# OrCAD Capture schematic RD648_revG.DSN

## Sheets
1 Mechanical Parts: size B
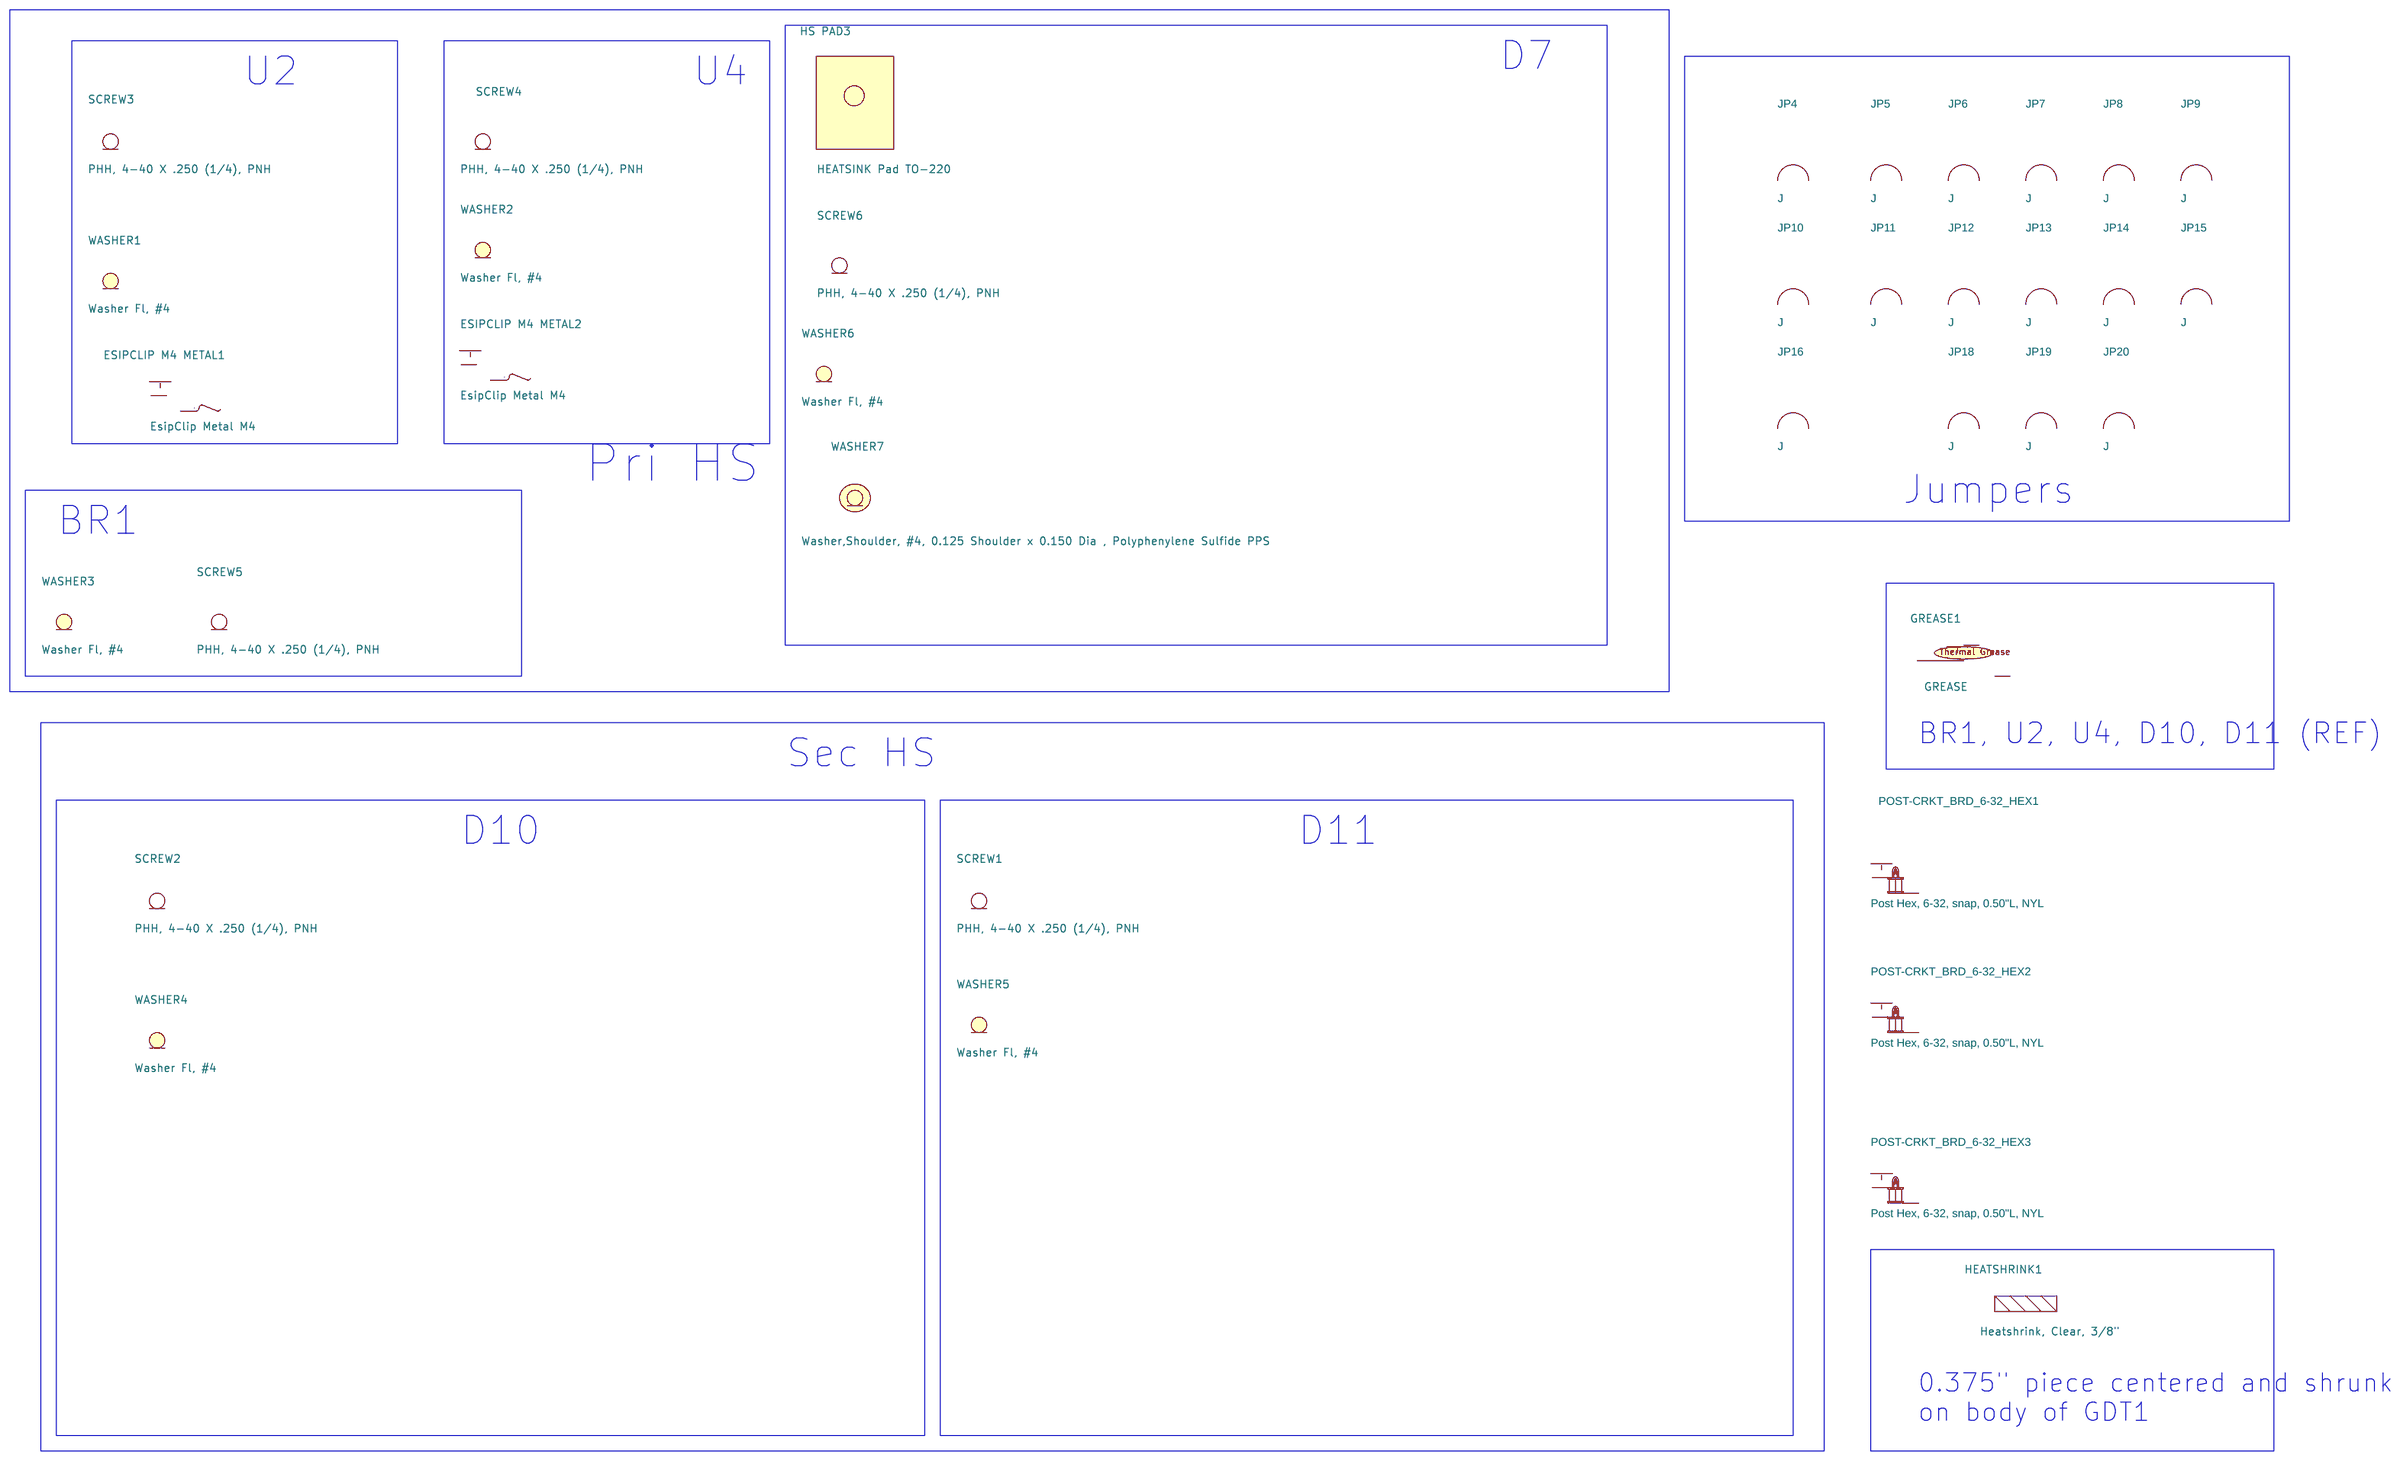
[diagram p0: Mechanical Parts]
2 1st Stage (PFC): size C
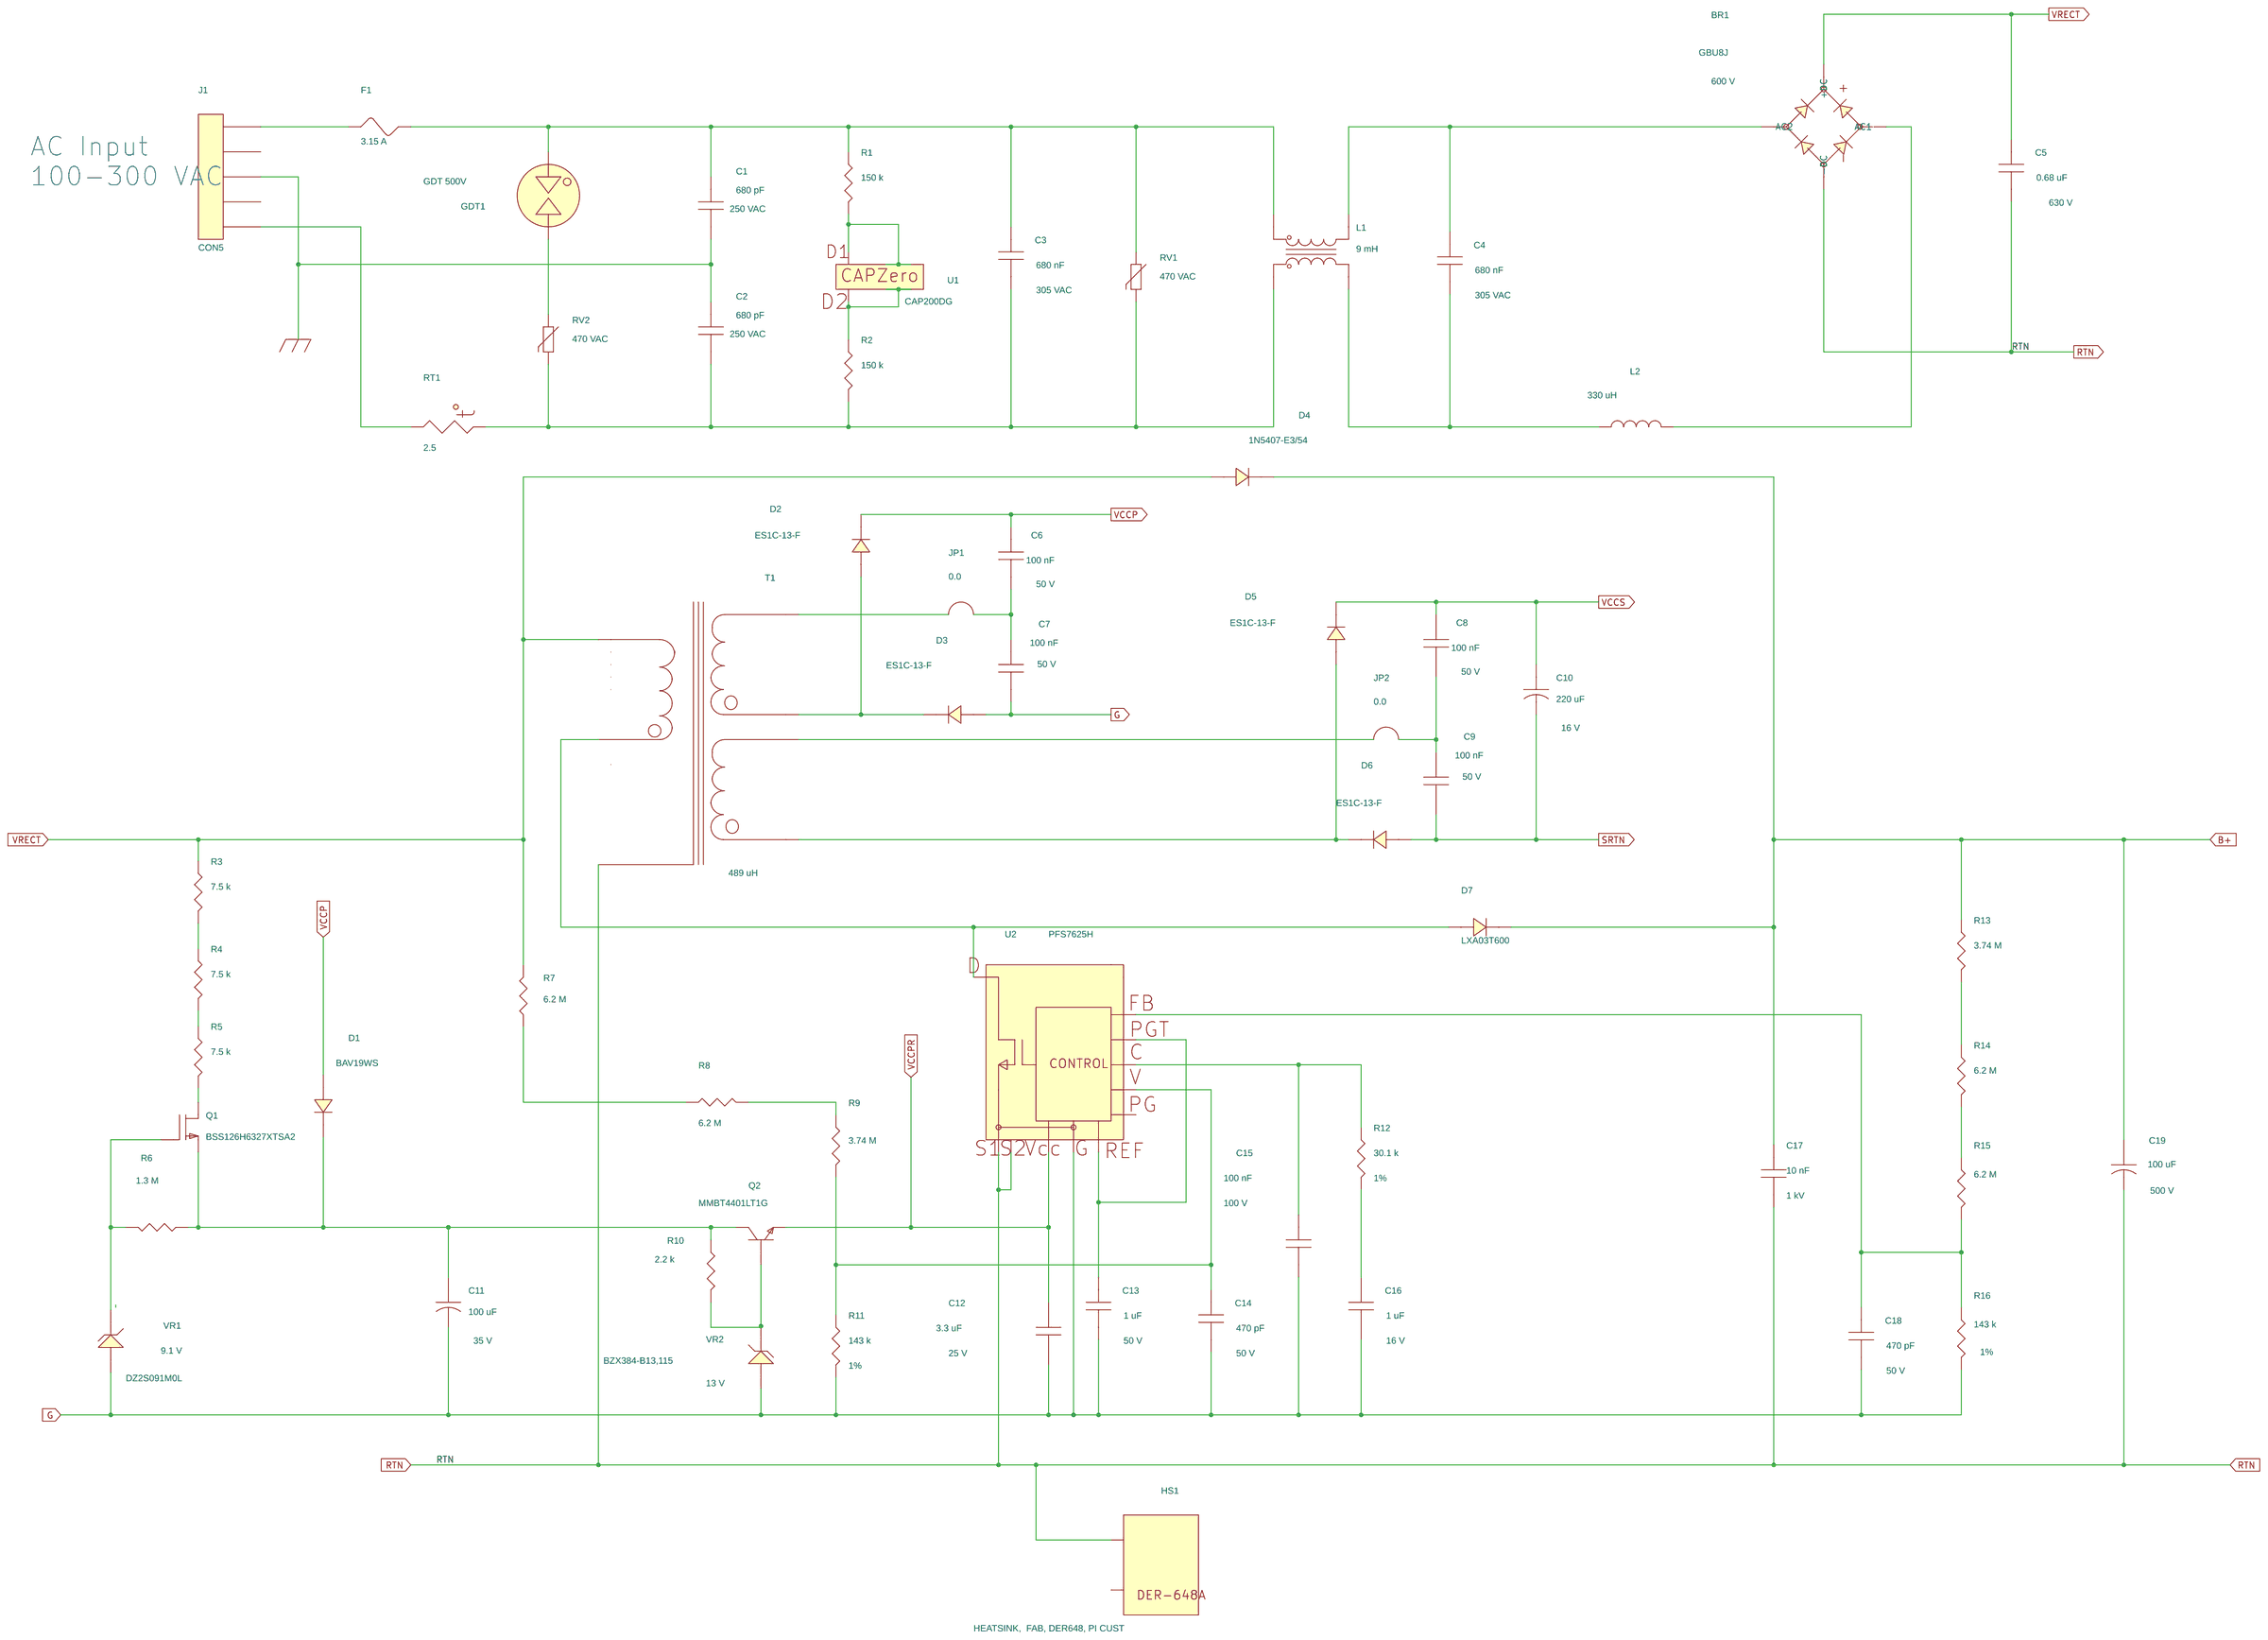
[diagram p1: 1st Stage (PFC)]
3 2nd Stage (LLC): size C
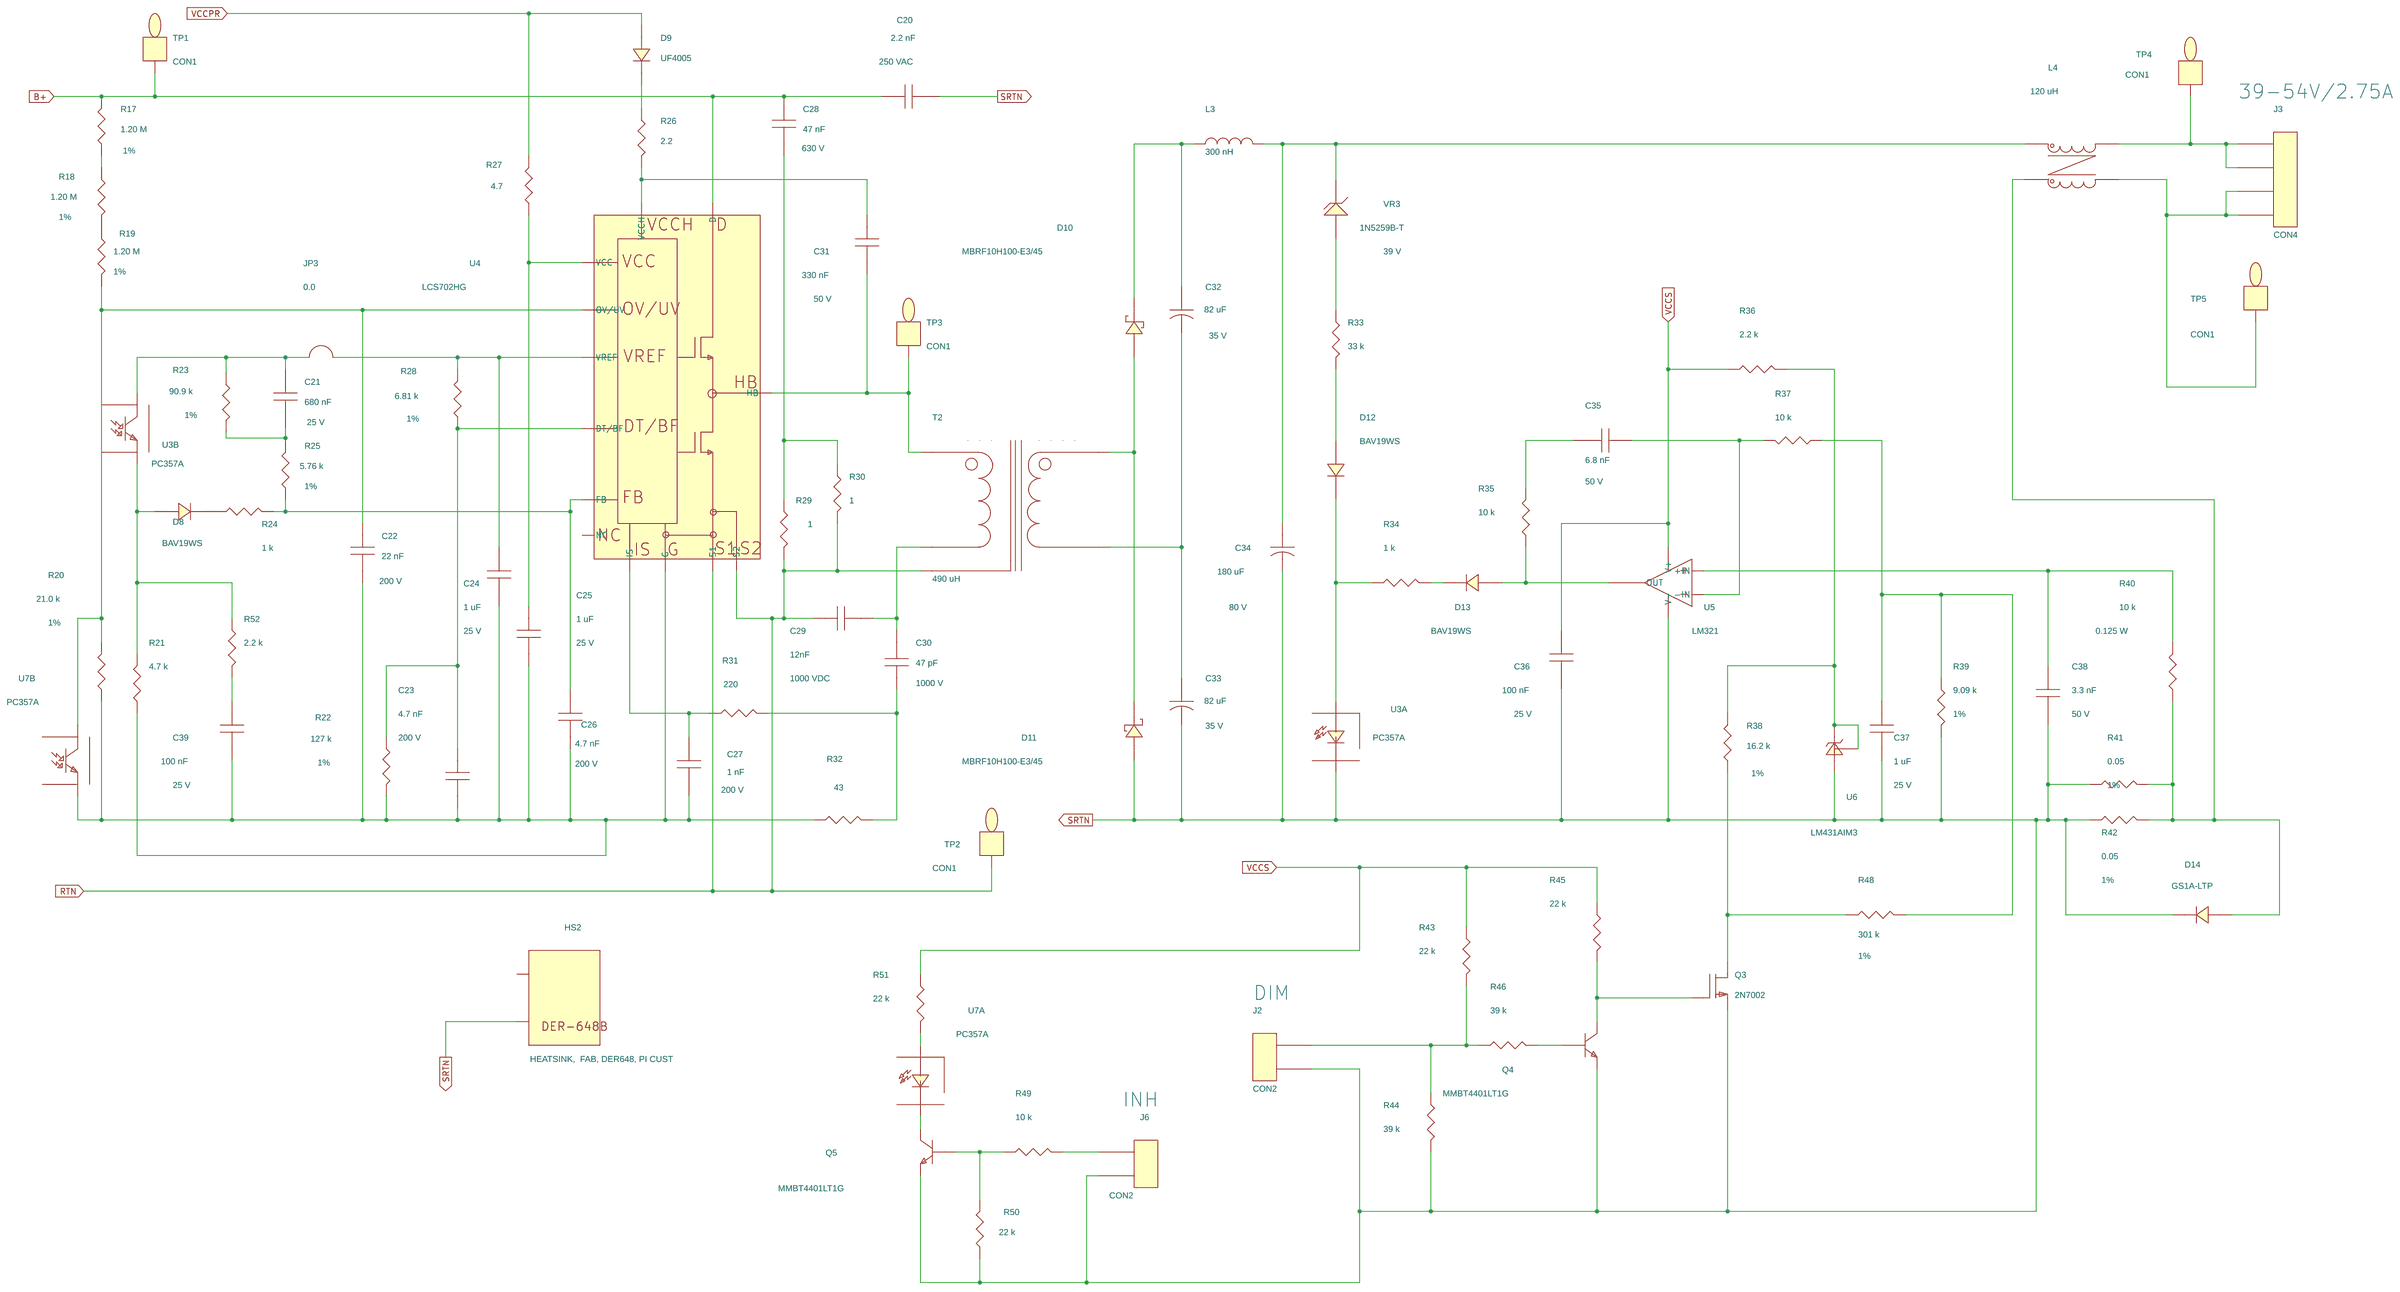
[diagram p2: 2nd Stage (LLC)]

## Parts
sheet 1st Stage (PFC)
BR1  GBU8J  [pidaxbridgegbu8]
C1  680 pF  [pinpycaprad470x210ls380040]
C2  680 pF  [pinpycaprad470x210ls380040]
C3  680 nF  [pinpxcaprad710x430720040]
C4  680 nF  [pinpxcaprad710x430720040]
C5  0.68 uF  [pi_np_caprad18p2x10ls15mmd050]
C6  100 nF  [pismc0805]
C7  100 nF  [pismc0805]
C8  100 nF  [pismc0805]
C9  100 nF  [pismc0805]
C10  220 uF  [pipolcapcyld250ls100030]
C11  100 uF  [pipolcapcyld250ls100030]
C12  3.3 uF  [pismc0805]
C13  1 uF  [pismc0805]
C14  470 pF  [pismc0805]
C15  100 nF  [pismc0603]
C16  1 uF  [pismc0603]
C17  10 nF  [pi_np_cap250x200ls170d030]
C18  470 pF  [pismc0805]
C19  100 uF  [pipolcapclyD25mmLS10mmd086]
D1  BAV19WS  [pismsod323]
D2  ES1C-13-F  [pismdo214ac12]
D3  ES1C-13-F  [pismdo214ac12]
D4  1N5407-E3/54  [pidv300x200x060do15d0201ad]
D5  ES1C-13-F  [pismdo214ac12]
D6  ES1C-13-F  [pismdo214ac12]
D7  LXA03T600  [pidvt0220acreva]
F1  3.15 A  [pi_rst_microfuse]
GDT1  GDT 500V  [pi_axD8xL6mm050v]
HS1  HEATSINK,  FAB, DER648, PI CUST  [hs_2P_DER648a]
J1  CON5  [pi_hdr_5pin_ls156_lck]
JP1  0.0  [pismr1206]
JP2  0.0  [pismr1206]
L1  9 mH  [pi_ind_4p_500x1050ls450d46]
L2  330 uH  [pi_toroid_2p_550x950_ls480_d050]
Q1  BSS126H6327XTSA2  [pismsot23123_1]
Q2  MMBT4401LT1G  [pismsot23123_1]
R1  150 k  [pismr1206]
R2  150 k  [pismr1206]
R3  7.5 k  [pismr1206]
R4  7.5 k  [pismr1206]
R5  7.5 k  [pismr1206]
R6  1.3 M  [pismr0805]
R7  6.2 M  [pismr1206]
R8  6.2 M  [pismr1206]
R9  3.74 M  [pismr1206]
R10  2.2 k  [pismr0603]
R11  143 k  [pismr0805]
R12  30.1 k  [pismr0603]
R13  3.74 M  [pismr1206]
R14  6.2 M  [pismr1206]
R15  6.2 M  [pi14wresd100ls500d030]
R16  143 k  [pismr0603]
RT1  2.5  [pi_rad180x395ls235d031]
RV1  470 VAC  [pi_disc1100x290ls400x220d050]
RV2  470 VAC  [pidisc610x212ls295x95040]
T1  489 uH  [pi_pfc_DER648]
U1  CAP200DG  [pi_ic_smd_so8_capzero]
U2  PFS7625H  [pi_ic_esip16-13_slot_hpii]
VR1  DZ2S091M0L  [pi_sm_d_ssmini2p]
VR2  BZX384-B13,115  [pismsod323]
sheet 2nd Stage (LLC)
C20  2.2 nF  [pinpycaprad540x290ls400040]
C21  680 nF  [pismc0805]
C22  22 nF  [pismc0805]
C23  4.7 nF  [pismc0805]
C24  1 uF  [pismc1206]
C25  1 uF  [pismc1206]
C26  4.7 nF  [pismc0805]
C27  1 nF  [pismc0805]
C28  47 nF  [PI_NP395X200LS300D040]
C29  12nF  [pi_np_cap689x200ls590d030]
C30  47 pF  [pinpcaprad370x156250040]
C31  330 nF  [pinpcaprad200x100200030]
C32  82 uF  [pipolcapclyd320ls140030]
C33  82 uF  [pipolcapclyd320ls140030]
C34  180 uF  [pipolcapclyd500ls200040]
C35  6.8 nF  [pismc0805]
C36  100 nF  [pismc0603]
C37  1 uF  [pismc1206]
C38  3.3 nF  [pismc0805]
C39  100 nF  [pismc0603]
D8  BAV19WS  [pismsod323]
D9  UF4005  [pidax475x125040do41]
D10  MBRF10H100-E3/45  [pidvITO220FPAC]
D11  MBRF10H100-E3/45  [pidvITO220FPAC]
D12  BAV19WS  [pismsod323]
D13  BAV19WS  [pismsod323]
D14  GS1A-LTP  [pismdo214ac12]
HS2  HEATSINK,  FAB, DER648, PI CUST  [hs_2P_DER648b]
J2  CON2  [pi_molex_2pol]
J3  CON4  [PI_HDR_4PIN]
J6  CON2  [pi_molex_2pol]
JP3  0.0  [pismr1206]
L3  300 nH  [pi_OUT_DER648]
L4  120 uH  [pi_toroid_DER648CMC]
Q3  2N7002  [pismsot23123_1]
Q4  MMBT4401LT1G  [pismsot23123_1]
Q5  MMBT4401LT1G  [pismsot23123_1]
R17  1.20 M  [pismr1206]
R18  1.20 M  [pismr1206]
R19  1.20 M  [pismr1206]
R20  21.0 k  [pismr0805]
R21  4.7 k  [pismr0805]
R22  127 k  [pismr0805]
R23  90.9 k  [pismr0805]
R24  1 k  [pismr0805]
R25  5.76 k  [pismr0805]
R26  2.2  [pi14wresd100ls400d030]
R27  4.7  [pi14wresd100ls500d030]
R28  6.81 k  [pi14wresd100ls400d030]
R29  1  [pi14wvresd100ls100d030]
R30  1  [pi14wvresd100ls100d030]
R31  220  [pismr0603]
R32  43  [pismr0805]
R33  33 k  [pismr0805]
R34  1 k  [pismr0805]
R35  10 k  [pismr1206]
R36  2.2 k  [pismr0805]
R37  10 k  [pismr0603]
R38  16.2 k  [pismr1206]
R39  9.09 k  [pismr0603]
R40  10 k  [pi18wvresd80ls100d030]
R41  0.05  [pismr1206]
R42  0.05  [pismr1206]
R43  22 k  [pismr0603]
R44  39 k  [pismr0603]
R45  22 k  [pismr0603]
R46  39 k  [pismr0603]
R48  301 k  [pismr1206]
R49  10 k  [pismr0603]
R50  22 k  [pismr0603]
R51  22 k  [pismr0603]
R52  2.2 k  [pismr0603]
T2  490 uH  [pi_bobbin_etd34_12p_cutout]
TP1  CON1  [pitpkeystone125x125]
TP2  CON1  [pitpkeystone125x125]
TP3  CON1  [pitpkeystone125x125]
TP4  CON1  [pitpkeystone125x125]
TP5  CON1  [pitpkeystone125x125]
U3  PC357A  [pi_4_smd]  (sections A,B)
U4  LCS702HG  [pi_ic_esip16-13_oval_slot]
U5  LM321  [pismsot235]
U6  LM431AIM3  [pismsot23123]
U7  PC357A  [pi_4_smd]  (sections A,B)
VR3  1N5259B-T  [pidax375x070030do35]
sheet Mechanical Parts
ESIPCLIP M4 METAL1  EsipClip Metal M4
ESIPCLIP M4 METAL2  EsipClip Metal M4
GREASE1  GREASE
HEATSHRINK1  Heatshrink, Clear, 3/8"
HS PAD3  HEATSINK Pad TO-220
JP4  J  [pi_jumper600-18awg-sld]
JP5  J  [pi_jumper400_d020]
JP6  J  [pi_jumper300_d020]
JP7  J  [pi_jumper1000_d020]
JP8  J  [pi_jumper1200_d020]
JP9  J  [pi_jumper300_d020]
JP10  J  [pi_jumper300-18awg-sld]
JP11  J  [pi_jumper600_d020]
JP12  J  [pi_jumper200_d020]
JP13  J  [pi_jumper300_d020]
JP14  J  [pi_jumper900_d020]
JP15  J  [pi_jumper800_d020]
JP16  J  [pi_jumper600-18awg-sld]
JP18  J  [pi_jumper600_d020]
JP19  J  [pi_jumper300_d020]
JP20  J  [pi_jumper700_d020]
POST-CRKT_BRD_6-32_HEX1  Post Hex, 6-32, snap, 0.50"L, NYL  [pimtgholed156]
POST-CRKT_BRD_6-32_HEX2  Post Hex, 6-32, snap, 0.50"L, NYL  [pimtgholed156]
POST-CRKT_BRD_6-32_HEX3  Post Hex, 6-32, snap, 0.50"L, NYL  [pimtgholed156]
SCREW1  PHH, 4-40 X .250 (1/4), PNH
SCREW2  PHH, 4-40 X .250 (1/4), PNH
SCREW3  PHH, 4-40 X .250 (1/4), PNH
SCREW4  PHH, 4-40 X .250 (1/4), PNH
SCREW5  PHH, 4-40 X .250 (1/4), PNH
SCREW6  PHH, 4-40 X .250 (1/4), PNH
WASHER1  Washer Fl, #4
WASHER2  Washer Fl, #4
WASHER3  Washer Fl, #4
WASHER4  Washer Fl, #4
WASHER5  Washer Fl, #4
WASHER6  Washer Fl, #4
WASHER7  Washer,Shoulder, #4, 0.125 Shoulder x 0.150 Dia , Polyphenylene Sulfide PPS

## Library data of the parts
BR1 = DISCRETE_BRIDGE_+~~-: Disp_Voltage: 600 V; Part Number: 15-00720-00; ROOM: 2
C1 C2 = CAP_NP: Disp_Voltage: 250 VAC; Part Number: 20-00374-00; ROOM: 2; Tol: 20; Voltage: 250 VAC
C3 C4 = CAP_NP: ALT_SYMBOLS: pinpxcaprad710x430720040_h; Disp_Voltage: 305 VAC; FPLIST: pinpxcaprad710x430720040,pinpxcaprad710x430720040_h; Part Number: 20-09129-00; ROOM: 2; Voltage: 305 VAC
C5 = CAP_NP: Disp_Voltage: 630 V; FPLIST: pi_np_caprad717x472ls590d050,pi_np_caprad18p2x10ls15mmd050; Part Number: 20-08970-00; Voltage: 630 VDC
C6-C9 = CAP_NP: Disp_Voltage: 50 V; Part Number: 20-00904-00; Voltage: 50 V
C10 = CAP_POL: Disp_Voltage: 16 V; Part Number: 20-00080-00; Voltage: 16 V
C11 = CAP_POL: ALT_SYMBOLS: pipolcapclyd250ls100d30h590; Disp_Voltage: 35 V; FPLIST: pipolcapcyld250ls100030,pipolcapclyd250ls100d30h590; Part Number: 20-00117-00; Voltage: 35 V
C12 = CAP_NP: Disp_Voltage: 25 V; Part Number: 20-01041-00; ROOM: 2; Voltage: 25 V
C13 = CAP_NP: Disp_Voltage: 50 V; Part Number: 20-09146-00; ROOM: 2; Voltage: 50 V
C14 C18 = CAP_NP: Disp_Voltage: 50 V; Part Number: 20-00205-00; ROOM: 2; Voltage: 50 V
C15 = CAP_NP: Disp_Voltage: 100 V; Part Number: 20-00749-00; ROOM: 2; Voltage: 100 V
C16 = CAP_NP: Disp_Voltage: 16 V; Part Number: 20-00540-00; ROOM: 2; Voltage: 16 V
C17 = CAP_NP: Disp_Voltage: 1 kV; Part Number: 20-00906-00; ROOM: 2; Tol: 20; Voltage: 1 kV
C19 = CAP_POL: Disp_Voltage: 500 V; Part Number: 20-09128-00; ROOM: 2; Voltage: 500 V
D1 = DIODE: Part Number: 15-00658-00; ROOM: 2
D2 D3 D5 D6 = DIODE: Part Number: 15-00352-00
D4 = DIODE: ALT_SYMBOLS: pidax800x225060do15do201ad,pidv300x200x060do14wbead,pidv600x200x060do14; FPLIST: pidv300x200x060do15d0201ad,pidax800x225060do15do201ad,pidv300x200x060do14wbead,pidv600x200x060do14; Part Number: 15-00798-00; ROOM: 2
D7 = DIODE: ALT_SYMBOLS: PI_TO220; FPLIST: pidvt0220acreva,PI_TO220; Part Number: 15-00848-00; ROOM: 2
F1 = FUSE: ALT_SYMBOLS: pirstmicrofusehoz; FPLIST: pi_rst_microfuse,pirstmicrofusehoz; Part Number: 40-00071-00; ROOM: 2
GDT1 = GDT: FPLIST: pi_axD8xL6mm050,pi_axD8xL6mm050v; Part Number: 66-00248-00
HS1 = hs_2P_DER648a: Part Number: 61-00226-01
J1 = CON5: Part Number: 35-00275-00
JP1 JP2 = JUMPER_1: Part Number: 05-03160-00
L1 = INDUCTOR_4P_revB: Part Number: 30-00235-00
L2 = INDUCTOR: Part Number: 32-00295-00; ROOM: 2
Q1 = FET_N_GSD: Part Number: 50-00253-00
Q2 = NPN_BEC: Part Number: 55-00152-00; ROOM: 2
R1 R2 = R: Part Number: 05-01404-00; ROOM: 2
R3-R5 = R: Part Number: 05-01373-00; ROOM: 2
R6 = R: Part Number: 05-01594-00; ROOM: 2
R7 R8 R14 = R: Part Number: 05-01440-00; ROOM: 2
R9 R13 = R: Part Number: 05-05572-00; ROOM: 2
R10 = R: Part Number: 05-01696-00; ROOM: 2
R11 = R: Disp_Tol: 1%; Part Number: 05-00795-00; ROOM: 2
R12 = R: Disp_Tol: 1%; Part Number: 05-03230-00; ROOM: 2
R15 = R: ALT_SYMBOLS: pi14wvresd100ls200d030,pi14wresd100ls400d030,pi14wresd100ls500d030; FPLIST: pi14wvresd100ls100d030,pi14wvresd100ls200d030,pi14wresd100ls400d030,pi14wresd100ls500d030; Part Number: 05-03122-00; ROOM: 2
R16 = R: Disp_Tol: 1%; Part Number: 05-01189-00; ROOM: 2
RT1 = THERMISTOR: ALT_SYMBOLS: pirad550x410ls300040_h; FPLIST: pi_rad180x395ls235d031,pirad550x410ls300040_h; Part Number: 90-00038-00; ROOM: 2
RV1 = VARISTOR: Part Number: 85-00050-00
RV2 = VARISTOR: Part Number: 85-00047-00
T1 = PFC_7p_DER648_0: Part Number: 30-00475-00
U1 = CAPZero: Part Number: 10-00958-00; ROOM: 2
U2 = HIPERPFS-4-eSIP-16G: ALT_SYMBOLS: pi_ic_esip16-13_socket_hpii,pi_ic_esip16-13_oval_hpii,pi_ic_eesip_socket; FPLIST: pi_ic_esip16-13_slot_hpii,pi_ic_esip16-13_socket_hpii,pi_ic_esip16-13_oval_hpii,pi_ic_eesip_socket; Part Number: 10-00989-00; ROOM: 2
VR1 = DIODE_ZENER: Disp_Voltage: 9.1 V; Part Number: 15-01007-00; ROOM: 2
VR2 = DIODE_ZENER: Disp_Voltage: 13 V; Part Number: 15-00819-00; ROOM: 2
C20 = CAP_NP: ALT_SYMBOLS: pinpycaprad540x290ls400040h; Disp_Voltage: 250 VAC; FPLIST: pinpycaprad540x290ls400040,pinpycaprad540x290ls400040h; Part Number: 20-00376-00; ROOM: 3; Voltage: 250 VAC
C21 = CAP_NP: Disp_Voltage: 25 V; Part Number: 20-08729-00; ROOM: 3; Voltage: 25 V
C22 = CAP_NP: Disp_Voltage: 200 V; Part Number: 20-00763-00; ROOM: 3; Voltage: 200 V
C23 = CAP_NP: COMPGROUP: 2; Disp_Voltage: 200 V; Layout PCB Footprint: PI_SM/C_0805; Part Number: 20-08570-00; ROOM: 3; Tol: 10; Voltage: 200 V
C24 C25 = CAP_NP: Disp_Voltage: 25 V; Part Number: 20-00897-00; ROOM: 3; Voltage: 25 V
C26 = CAP_NP: COMPGROUP: 2; Disp_Voltage: 200 V; Part Number: 20-08570-00; ROOM: 3; Tol: 10; Voltage: 200 V
C27 = CAP_NP: COMPGROUP: 2; Disp_Voltage: 200 V; Layout PCB Footprint: PI_SM/C_0805; Part Number: 20-00737-00; ROOM: 3; Tol: 10; Voltage: 200 V
C28 = CAP_NP: Disp_Voltage: 630 V; Part Number: 20-08702-00; ROOM: 3; Voltage: 630 V
C29 = CAP_NP: Disp_Voltage: 1000 VDC; Part Number: 20-09134-00; ROOM: 3; Voltage: 1000 VDC
C30 = CAP_NP: COMPGROUP: 2; Disp_Voltage: 1000 V; PCB Editor PCBFP: pinpcaprad180x160200030; Part Number: 20-08564-00; ROOM: 3; Tol: 5; Voltage: 1000 V
C31 = CAP_NP: Disp_Voltage: 50 V; Part Number: 20-00935-00; ROOM: 3; Voltage: 50 V
C32 C33 = CAP_POL: ALT_SYMBOLS: pipolcapclyd320ls140d30h470; Disp_Voltage: 35 V; FPLIST: pipolcapclyd320ls140030,pipolcapclyd320ls140d30h470; Part Number: 20-08725-00; ROOM: 4; Voltage: 35 V
C34 = CAP_POL: ALT_SYMBOLS: pipolcapclyd500ls200040690lh; Disp_Voltage: 80 V; FPLIST: pipolcapclyd500ls200040,pipolcapclyd500ls200040690lh; Part Number: 20-01185-00; ROOM: 4; Voltage: 80 V
C35 = CAP_NP: Disp_Voltage: 50 V; Part Number: 20-08754-00; ROOM: 4; Voltage: 50 V
C36 C39 = CAP_NP: Disp_Voltage: 25 V; Part Number: 20-00528-00; ROOM: 4; Voltage: 25 V
C37 = CAP_NP: Disp_Voltage: 25 V; Part Number: 20-00897-00; ROOM: 4; Voltage: 25 V
C38 = CAP_NP: Disp_Voltage: 50 V; Part Number: 20-00215-00; ROOM: 4; Voltage: 50 V
D8 = DIODE: Part Number: 15-00658-00; ROOM: 3
D9 = DIODE: ALT_SYMBOLS: pidax475x125040do41,pidax390x125040do41; FPLIST: pidv200x110x040do41,pidax475x125040do41,pidax390x125040do41; Part Number: 15-00109-00; ROOM: 3
D10 D11 = DIODE_SCHOTTKY: Part Number: 15-01280-00; ROOM: 4
D12 D13 = DIODE: Part Number: 15-00658-00; ROOM: 4
D14 = DIODE: Part Number: 15-01110-00; ROOM: 4
HS2 = hs_2P_DER648b: Part Number: 61-00227-01
J2 J6 = CON2: Part Number: 35-00137-00
J3 = CON4: COMPGROUP: 2; Part Number: 35-00003-00; ROOM: 4
JP3 = JUMPER_1: Part Number: 05-03160-00; ROOM: 3
L3 = INDUCTOR: Part Number: 32-00363-00
L4 = TORRID_4P_12_34: Part Number: 32-00362-00
Q3 = FET_N_GSD: Part Number: 50-00103-00
Q4 Q5 = NPN_BEC: Part Number: 55-00152-00
R17 = R: Disp_Tol: 1%; Part Number: 05-03151-00
R18 R19 = R: COMPGROUP: 2; Disp_Tol: 1%; Part Number: 05-03151-00; Tol: 1%
R20 = R: Disp_Tol: 1%; Part Number: 05-00715-00
R21 = R: COMPGROUP: 2; Part Number: 05-01535-00; Tol: 5%
R22 = R: Disp_Tol: 1%; Part Number: 05-00790-00; ROOM: 3
R23 = R: Disp_Tol: 1%; Part Number: 05-00776-00; ROOM: 3
R24 = R: Part Number: 05-01519-00; ROOM: 3
R25 = R: Disp_Tol: 1%; Part Number: 05-03379-00; ROOM: 3
R26 = R: ALT_SYMBOLS: pi14wvresd100ls200d030,pi14wresd100ls400d030,pi14wresd100ls500d030; FPLIST: pi14wvresd100ls100d030,pi14wvresd100ls200d030,pi14wresd100ls400d030,pi14wresd100ls500d030; Part Number: 05-02443-00; ROOM: 3
R27 = R: ALT_SYMBOLS: pi14wvresd100ls200d030,pi14wresd100ls400d030,pi14wresd100ls500d030; FPLIST: pi14wvresd100ls100d030,pi14wvresd100ls200d030,pi14wresd100ls400d030,pi14wresd100ls500d030; Part Number: 05-02451-00; ROOM: 3
R28 = R: ALT_SYMBOLS: pi14wvresd100ls200d030,pi14wresd100ls400d030,pi14wresd100ls500d030; Disp_Tol: 1%; FPLIST: pi14wvresd100ls100d030,pi14wvresd100ls200d030,pi14wresd100ls400d030,pi14wresd100ls500d030; Part Number: 05-02056-00; ROOM: 3
R29 R30 = R: ALT_SYMBOLS: pi14wvresd100ls200d030,pi14wresd100ls400d030,pi14wresd100ls500d030; FPLIST: pi14wvresd100ls100d030,pi14wvresd100ls200d030,pi14wresd100ls400d030,pi14wresd100ls500d030; Part Number: 05-02435-00; ROOM: 3
R31 = R: Part Number: 05-01672-00; ROOM: 3
R32 = R: Part Number: 05-01486-00; ROOM: 3
R33 = R: Part Number: 05-01555-00; ROOM: 4
R34 = R: Part Number: 05-01519-00; ROOM: 4
R35 = R: Part Number: 05-01376-00; ROOM: 4
R36 = R: Part Number: 05-01527-00; ROOM: 4
R37 R49 = R: Part Number: 05-01712-00
R38 = R: Disp_Tol: 1%; Part Number: 05-00309-00
R39 = R: Disp_Tol: 1%; Part Number: 05-01170-00; ROOM: 4
R40 = R: ALT_SYMBOLS: pi18wresd080ls300d030; Disp_Power: 0.125 W; FPLIST: pi18wvresd80ls100d030,pi18wresd080ls300d030; Part Number: 05-02361-00; ROOM: 4
R41 R42 = R: Disp_Tol: 1%; Part Number: 05-06425-00; ROOM: 4
R43 R45 R50 R51 = R: Part Number: 05-01720-00
R44 R46 = R: Part Number: 05-01726-00
R48 = R: Disp_Tol: 1%; Part Number: 05-00431-00
R52 = R: Part Number: 05-01696-00
T2 = pi_llcxfrmr_DER648_0: Part Number: 25-01134-00
TP1-TP3 = TESTPOINT: Part Number: 35-00042-00; ROOM: 3
TP4 = TESTPOINT: Part Number: 35-00043-00; ROOM: 4
TP5 = TESTPOINT: Part Number: 35-00042-00; ROOM: 4
U3 U7 = OPTO_A_B: Part Number: 53-00033-00
U4 = LC_SWITCH_Rev03: FPLIST: pi_ic_esip16-13_slot,pi_ic_esip16-13_socket_sl0t,pi_ic_esip16-13_oval_slot; Part Number: 10-00342-00; ROOM: 3
U5 = LM321_SOT23-5: Part Number: 45-00049-00; ROOM: 4
U6 = TL431_SOT-23_CAR: Part Number: 45-00268-00; ROOM: 4
VR3 = DIODE_ZENER: Disp_Voltage: 39 V; FPLIST: pidv200x080x030do35,pidax375x070030do35; Part Number: 15-00762-00; ROOM: 4
ESIPCLIP M4 METAL1 ESIPCLIP M4 METAL2 = EsipClip_Metal_M4: Part Number: 60-00042-00
GREASE1 = Grease_Therm: Part Number: 60-00035-00
HEATSHRINK1 = HEATSHRINK: Part Number: 62-00008-00
HS PAD3 = HS_Pad-T0-220: Part Number: 66-00141-00
JP4 JP16 = JUMPER_1: Part Number: 65-00084-00
JP5 = JUMPER_1: Part Number: 65-00600-02
JP6 JP9 JP13 JP19 = JUMPER_1: Part Number: 65-00600-01
JP7 = JUMPER_1: Part Number: 65-00600-08
JP8 = JUMPER_1: Part Number: 65-00600-10
JP10 = JUMPER_1: Part Number: 65-00081-00
JP11 JP18 = JUMPER_1: Part Number: 65-00600-04
JP12 = JUMPER_1: Part Number: 65-00600-00
JP14 = JUMPER_1: Part Number: 65-00600-07
JP15 = JUMPER_1: Part Number: 65-00600-06
JP20 = JUMPER_1: Part Number: 65-00600-05
POST-CRKT_BRD_6-32_HEX1-POST-CRKT_BRD_6-32_HEX3 = POST_CRKT_BRD_6-32_HEX: Part Number: 76-00038-00
SCREW1-SCREW6 = SCR_4-40: Part Number: 75-00001-00
WASHER1-WASHER6 = WASH_FLAT_4: Part Number: 75-00164-00
WASHER7 = WASH_SHLDR_4: Part Number: 75-00155-00

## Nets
GND_EARTH: C1.2 C2.1 J1.3
VCCP: C6.1 D1.2 D2.1
VCCPR: C12.1 D9.2 Q2.2(EMITTER) R27.1 U2.1(Vcc)
VCCS: C8.1 C10.1 C36.1 D5.1 R36.1 R43.1 R45.1 R51.1 U5.5(V+)
B+: C17.1 C19.1 C20.1 C28.1 D4.1 D7.1 R13.1 R17.2 TP1.1 U4.16(D)
G: C7.2 C11.2 C12.2 C13.2 C14.2 C15.2 C16.2 C18.2 D3.2 R11.2 R16.1 U2.4(G) VR1.2 VR2.2
K: U2.16(K)
NC: U2.14(NC)
RTN: BR1.4(-DC) C5.2 C17.2 C19.2 C29.1 HS1.2 R29.2 R30.2 T1.7 T2.1 TP2.1 U2.10(S1) U2.11(SOURCE) U4.10(S1) U4.11(S2)
SRTN: C9.2 C10.2 C20.2 C33.2 C34.2 C36.2 C37.2 C38.2 D6.2 D11.2 D14.1 HS2.1 J2.1 J6.1 Q3.2(S) Q4.2(EMITTER) Q5.2(EMITTER) R39.2 R41.2 R42.2 R44.2 R50.1 U3.2(C) U5.2(V-) U6.2(A)
VRECT: BR1.1(+DC) C5.1 D4.2 R3.1 R7.2 T1.12
N11361629: BR1.3(AC2) C4.1 L1.4
N11361637: BR1.2(AC1) L2.2
N11361645: F1.1 J1.1
N11361649: C1.1 C3.1 F1.2 GDT1.1 L1.3 R1.1 RV1.1
N11361735: J1.5 RT1.1
N11361765: R1.2 U1.1(NC1) U1.2(D1) U1.3(NC2) U1.4(NC3)
N11361893: R2.1 U1.5(NC4) U1.6(NC5) U1.7(D2) U1.8(NC8)
N11361909: C2.2 C3.2 L1.1 R2.2 RT1.2 RV1.2 RV2.2
N11361917: C4.2 L1.2 L2.1
N11368602: R3.2 R4.1
N11368632: D7.2 T1.9 U2.13(D)
N11368730: R13.2 R14.1
N11368734: R4.2 R5.1
N11368746: C18.1 R15.1 R16.2 U2.7(FB)
N11368794: C15.1 R12.1 U2.6(C)
N11368862: Q1.3(D) R5.2
N11368870: R7.1 R8.1
N11368874: R8.2 R9.1
N11368882: C14.1 R9.2 R11.1 U2.5(V)
N11368906: R14.2 R15.2
N11368928: C11.1 D1.1 Q1.2(S) Q2.3(COLLECTOR) R6.2 R10.1
N11368966: Q1.1(G) R6.1 VR1.1
N11368994: C13.1 U2.3(REF) U2.9(PGT)
N11369180: C16.1 R12.2
N11369212: Q2.1(BASE) R10.2 VR2.1
N11375827: D9.1 R26.1
N11375939: R17.1 R18.1
N11375959: C31.1 R26.2 U4.14(VCCH)
N11375963: C28.2 R29.1 R30.1
N11375997: C25.1 R27.2 U4.1(VCC)
N11376097: C31.2 T2.2 TP3.1 U4.13(HB)
N11376117: C22.1 R19.2 R20.1 U4.5(OV/UV) U7.4(C)
N11376317: C21.1 JP3.2 R23.1 U3.4(C)
N11376341: C24.1 JP3.1 R28.1 U4.3(VREF)
N11376649: C21.2 R23.2 R25.1
N11376707: C23.1 R22.1 R28.2 U4.7(DT/BF)
N11376799: D8.2 R21.1 R52.1 U3.3(E)
N11376923: C26.1 R24.2 R25.2 U4.6(FB)
N11377121: C22.2 C23.2 C24.2 C25.2 C26.2 C27.2 C39.2 R20.2 R21.2 R22.2 R32.1 U4.4(G) U7.3(E)
N11377143: C27.1 R31.1 U4.8(IS)
N11377647: C30.1 R31.2 R32.2
N11387015: C6.2 C7.1 JP1.2
N11387049: D2.2 D3.1 T1.10
N11394983: C29.2 C30.2 T2.3
N11395044: D10.2 D11.1 T2.10
N11395340: C32.1 D10.1 L3.1
N11396434: D5.2 D6.1 T1.6
N11396456: C8.2 C9.1 JP2.2
N11396474: JP2.1 T1.5
N11404287: C34.1 L3.2 L4.1 VR3.1
N11405404: D14.2 L4.3 R40.1 R41.1 R42.1
N11406552: D12.1 R34.1 U3.1(A)
N11407305: D13.2 R35.1 U5.4(OUT)
N11407588: R36.2 R38.2 U6.1(C) U6.3(VREF)
N11410539: C38.1 R40.2 U5.1(+IN)
N11410712: C35.1 R37.2 U5.3(-IN)
N11441238: Q3.1(G) Q4.3(COLLECTOR) R45.2
N11449111: JP1.1 T1.11
N11457086: D12.2 R33.2
N11457090: R33.1 VR3.2
N11461450: D13.1 R34.2
N11464509: C37.1 R37.1 R39.1 R48.2
N11469796: Q3.3(D) R38.1 R48.1
N11480149: C35.2 R35.2
N11512058: J3.1 J3.2 L4.2 TP4.1
N11512267: J3.3 J3.4 L4.4 TP5.1
N11532854: J2.2 R43.2 R44.1 R46.1
N11552445: Q4.1(BASE) R46.2
N11579928: Q5.3(COLLECTOR) U7.2(C)
N11579932: Q5.1(BASE) R49.1 R50.2
N11579936: J6.2 R49.2
N11634216: C32.2 C33.1 T2.8
N11634313: C39.1 R52.2
N11640064: GDT1.2 RV2.1
N11642887: R51.2 U7.1(A)
N11675648: R18.2 R19.1
N11675649: D8.1 R24.1

Not connected (* = marked no-connect by the designer): HS1 1; HS2 2; J1 2 4; JP4 1 2; JP5 1 2; JP6 1 2; JP7 1 2; JP8 1 2; JP9 1 2; JP10 1 2; JP11 1 2; JP12 1 2; JP13 1 2; JP14 1 2; JP15 1 2; JP16 1 2; JP18 1 2; JP19 1 2; JP20 1 2; POST-CRKT_BRD_6-32_HEX1 1; POST-CRKT_BRD_6-32_HEX2 1; POST-CRKT_BRD_6-32_HEX3 1; T1 1 2 3 4 8; T2 4 5 6 7 9 11 12; U2 8(PG); U4 9(NC)

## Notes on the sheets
sheet 1
- D7
- U2
- U4
- Pri HS
- Jumpers
- BR1
- BR1, U2, U4, D10, D11 (REF)
- Sec HS
- D10
- D11
- 0.375" piece centered and shrunk
  on body of GDT1
sheet 2
- AC Input
  100-300 VAC
sheet 3
- 39-54V/2.75A
- DIM
- INH
